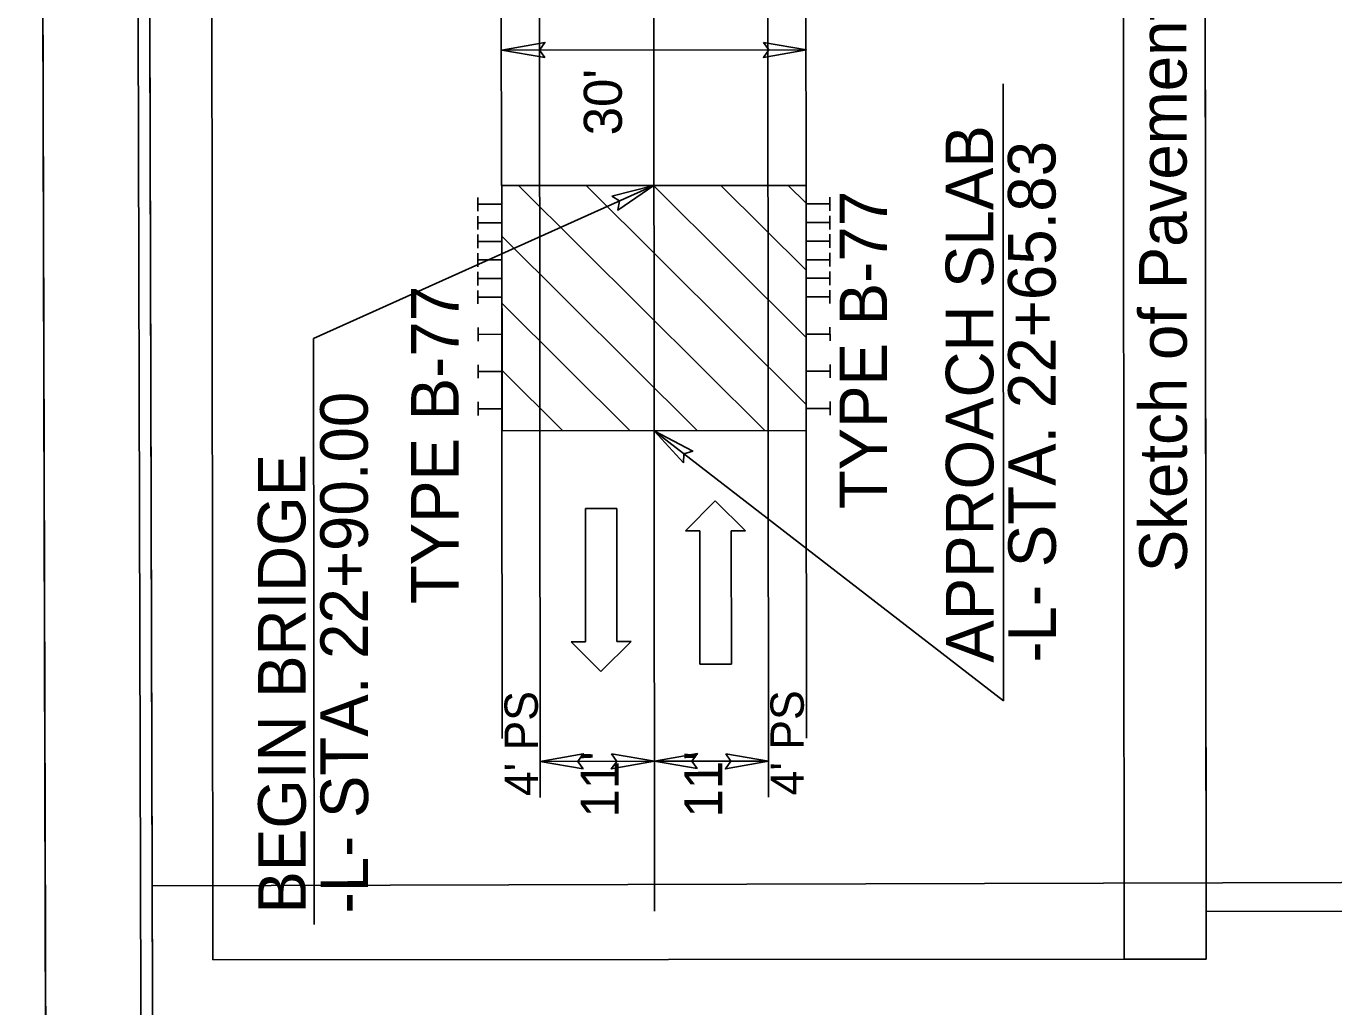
# Model space of a CAD drawing. Extents: x 1373110 to 1374209, y 550682 to 552749.
# Drawn here: x 1373109.6 to 1373384.5, y 551034.3 to 551240.4 of the extents above; entities that cross this region are included whole.
import ezdxf

# ---------------------------------------------------------------- set-up
doc = ezdxf.new("R2010")
doc.units = 0
for name, color, linetype in [('Prop Approach Slab Hatching', 7, 'Continuous'), ('Prop Drainage Structure Drop Inlet Grate 2 Narrow Slots and Flat Grates 840 29 TB Label', 7, 'Continuous'), ('Prop Drainage Structure Gutter Shoulder Berm Label', 7, 'Continuous'), ('Prop Drainage Structure Pipe Alternate 18in', 7, 'Continuous'), ('Prop Drainage Structure Pipe Alternate 18in Label', 7, 'Continuous'), ('Prop Drainage Structure Pipe CSP 15in Label', 7, 'Continuous'), ('Prop Drainage Structure Pipe RCP 15in Class IV Label', 7, 'Continuous'), ('Prop Drainage Structure Pipe Removal Label', 7, 'Continuous'), ('Prop Drainage Structure Tops and Inverts LABEL', 7, 'Continuous'), ('Prop Earthen Structure Base Ditch with Rip Rap Detail CELL', 7, 'Continuous'), ('Prop Earthen Structure Base Ditch with Rip Rap Detail Label', 7, 'Continuous'), ('Prop Earthen Structure V Ditch Special Lateral Detail Label', 7, 'Continuous'), ('Prop Erosion Rip Rap At Embankment Detail Label', 7, 'Continuous'), ('Prop Erosion Rip Rap Class B Label', 7, 'Continuous'), ('Prop Erosion Rip Rap Class I', 7, 'Continuous'), ('Prop Plan Preparation Sketches Hydraulic Ditch', 7, 'Continuous'), ('Prop Roadway Bridge', 7, 'Continuous'), ('Prop SS Fill Line', 7, 'Continuous')]:
    doc.layers.add(name, color=color, linetype=linetype)

msp = doc.modelspace()

# ---------------------------------------------------------------- linework, layer by layer
at = {"layer": 'Prop Approach Slab Hatching'}
for p, q in [((1373209.4, 551306.44), (1373209.49, 551206.85)), ((1373273.53, 551206.9), (1373273.44, 551306.49)), ((1373209.49, 551206.85), (1373273.53, 551206.9))]:
    msp.add_line(p, q, dxfattribs=at)
at = {"layer": 'Prop Drainage Structure Drop Inlet Grate 2 Narrow Slots and Flat Grates 840 29 TB Label'}
for points in [[(1373132.1, 552509.76), (1373136.2, 551009.73), (1374186.2, 551012.6), (1374182.1, 552512.6)], [(1374186.2, 551012.6), (1373136.23, 551009.7), (1373132.64, 552309.68), (1373282.7, 552310.11), (1373282.16, 552510.14), (1374182.1, 552512.6)]]:
    msp.add_lwpolyline(points, close=True, dxfattribs=at)
at = {"layer": 'Prop Drainage Structure Gutter Shoulder Berm Label'}
msp.add_lwpolyline([(1374209.17, 550846.17), (1374204.56, 552529.67), (1373109.57, 552526.67), (1373114.17, 550843.18)], close=True, dxfattribs=at)
at = {"layer": 'Prop Drainage Structure Pipe Alternate 18in'}
for p, q in [((1373209.53, 551206.85), (1373209.57, 551159.97)), ((1373273.53, 551206.9), (1373273.57, 551160.03)), ((1373204.53, 551204.37), (1373204.54, 551201.51)), ((1373209.54, 551202.94), (1373204.54, 551202.94)), ((1373273.53, 551203), (1373278.53, 551203)), ((1373278.53, 551204.43), (1373278.53, 551201.57)), ((1373204.54, 551200.46), (1373204.54, 551197.6)), ((1373278.53, 551200.53), (1373278.53, 551197.66)), ((1373209.54, 551199.04), (1373204.54, 551199.03)), ((1373273.53, 551199.09), (1373278.53, 551199.1)), ((1373204.54, 551196.56), (1373204.54, 551193.69)), ((1373209.54, 551195.13), (1373204.54, 551195.13)), ((1373273.54, 551195.19), (1373278.54, 551195.19)), ((1373278.54, 551196.62), (1373278.54, 551193.76)), ((1373204.54, 551192.65), (1373204.55, 551189.79)), ((1373278.54, 551192.72), (1373278.54, 551189.85)), ((1373209.55, 551191.22), (1373204.55, 551191.22)), ((1373204.55, 551188.74), (1373204.55, 551185.88)), ((1373273.54, 551191.28), (1373278.54, 551191.28)), ((1373278.54, 551188.81), (1373278.54, 551185.95)), ((1373209.55, 551187.32), (1373204.55, 551187.31)), ((1373273.54, 551187.37), (1373278.54, 551187.38)), ((1373204.55, 551184.84), (1373204.55, 551181.97)), ((1373209.55, 551183.41), (1373204.55, 551183.41)), ((1373273.55, 551183.47), (1373278.55, 551183.47)), ((1373278.55, 551184.9), (1373278.55, 551182.04)), ((1373204.56, 551177.03), (1373204.56, 551174.16)), ((1373209.56, 551175.6), (1373204.56, 551175.59)), ((1373273.55, 551175.66), (1373278.55, 551175.66)), ((1373278.55, 551177.09), (1373278.56, 551174.23)), ((1373204.57, 551169.21), (1373204.57, 551166.35)), ((1373209.57, 551167.79), (1373204.57, 551167.78)), ((1373273.56, 551167.84), (1373278.56, 551167.85)), ((1373278.56, 551169.28), (1373278.56, 551166.42)), ((1373204.57, 551161.4), (1373204.57, 551158.54)), ((1373278.57, 551161.47), (1373278.57, 551158.6)), ((1373209.57, 551159.97), (1373204.57, 551159.97)), ((1373273.57, 551160.03), (1373278.57, 551160.03))]:
    msp.add_line(p, q, dxfattribs=at)
at = {"layer": 'Prop Drainage Structure Pipe Alternate 18in Label'}
for points in [[(1373218.59, 551233.8), (1373209.58, 551235.35), (1373218.63, 551236.95), (1373217.48, 551235.35)], [(1373264.58, 551236.94), (1373273.58, 551235.4), (1373264.54, 551233.79), (1373265.68, 551235.4)], [(1373232.68, 551204.6), (1373241.53, 551206.88), (1373233.93, 551201.71), (1373234.32, 551203.64)], [(1373247.75, 551148.59), (1373241.57, 551155.32), (1373249.71, 551151.06), (1373247.82, 551150.49)], [(1373226.63, 551084.3), (1373217.63, 551085.84), (1373226.68, 551087.45), (1373225.53, 551085.84)], [(1373232.63, 551087.4), (1373241.63, 551085.86), (1373232.58, 551084.25), (1373233.73, 551085.85)], [(1373250.63, 551084.32), (1373241.63, 551085.86), (1373250.68, 551087.47), (1373249.53, 551085.87)], [(1373256.63, 551087.42), (1373265.63, 551085.88), (1373256.58, 551084.27), (1373257.73, 551085.87)]]:
    msp.add_lwpolyline(points, close=True, dxfattribs=at)
at = {"layer": 'Prop Drainage Structure Pipe CSP 15in Label'}
msp.add_line((1373109.57, 552526.67), (1373114.17, 550843.18), dxfattribs=at)
at = {"layer": 'Prop Drainage Structure Pipe RCP 15in Class IV Label'}
msp.add_lwpolyline([(1373136.23, 551009.7), (1374186.2, 551012.6), (1374182.1, 552512.59), (1373343.59, 552510.3), (1373344.24, 552271.05), (1373132.76, 552270.47)], close=True, dxfattribs=at)
at = {"layer": 'Prop Drainage Structure Pipe Removal Label'}
for p, q in [((1373209.57, 551159.97), (1373209.64, 551090.66)), ((1373273.63, 551090.72), (1373273.57, 551160.03))]:
    msp.add_line(p, q, dxfattribs=at)
at = {"layer": 'Prop Drainage Structure Tops and Inverts LABEL'}
msp.add_lwpolyline([(1374189.13, 550859.12), (1374184.56, 552525.1), (1373129.58, 552522.23), (1373134.14, 550856.23)], close=True, dxfattribs=at)
at = {"layer": 'Prop Earthen Structure Base Ditch with Rip Rap Detail CELL'}
msp.add_lwpolyline([(1374186.06, 551062.6), (1374182.23, 552462.6), (1373343.73, 552460.31), (1373344.24, 552271.05), (1373132.76, 552270.47), (1373136.07, 551059.72)], close=True, dxfattribs=at)
at = {"layer": 'Prop Earthen Structure V Ditch Special Lateral Detail Label'}
for p, q in [((1373217.64, 551078.27), (1373217.32, 551435.22)), ((1373265.64, 551078.31), (1373265.32, 551435.27))]:
    msp.add_line(p, q, dxfattribs=at)
at = {"layer": 'Prop Erosion Rip Rap At Embankment Detail Label'}
for p, q in [((1373273.53, 551206.9), (1373209.53, 551206.85)), ((1373273.53, 551206.9), (1373209.57, 551206.85)), ((1373209.57, 551206.85), (1373209.61, 551155.29)), ((1373273.57, 551155.35), (1373273.53, 551206.9)), ((1373209.61, 551155.29), (1373273.57, 551155.35))]:
    msp.add_line(p, q, dxfattribs=at)
at = {"layer": 'Prop Erosion Rip Rap Class B Label'}
for points in [[(1374186.06, 551062.6), (1374182.23, 552462.6), (1373343.73, 552460.31), (1373344.24, 552271.05), (1373132.76, 552270.47), (1373136.07, 551059.72)], [(1374186.13, 551055.1), (1374185.31, 551891.66), (1374039.33, 551891.53), (1374038.82, 552461.52), (1373346.29, 552460.9), (1373346.46, 552271.64), (1373134.97, 552271.45), (1373135.76, 551468.67), (1373357.23, 551468.89), (1373357.64, 551054.29)]]:
    msp.add_lwpolyline(points, close=True, dxfattribs=at)
at = {"layer": 'Prop Erosion Rip Rap Class I'}
for p, q in [((1373248.2, 551134.3), (1373254.39, 551140.61)), ((1373254.39, 551140.61), (1373260.8, 551134.31)), ((1373233.72, 551139.01), (1373227.12, 551139)), ((1373227.12, 551139), (1373227.15, 551111)), ((1373233.75, 551111.01), (1373233.72, 551139.01)), ((1373251.2, 551134.3), (1373248.2, 551134.3)), ((1373251.22, 551106.3), (1373251.2, 551134.3)), ((1373260.8, 551134.31), (1373257.8, 551134.31)), ((1373257.8, 551134.31), (1373257.82, 551106.31)), ((1373227.15, 551111), (1373224.15, 551111)), ((1373224.15, 551111), (1373230.35, 551104.71)), ((1373230.35, 551104.71), (1373236.75, 551111.01)), ((1373236.75, 551111.01), (1373233.75, 551111.01)), ((1373257.82, 551106.31), (1373251.22, 551106.3))]:
    msp.add_line(p, q, dxfattribs=at)
at = {"layer": 'Prop Plan Preparation Sketches Hydraulic Ditch'}
for p, q in [((1373209.58, 551235.35), (1373273.58, 551235.4)), ((1373314.92, 551228.23), (1373315.04, 551098.57)), ((1373241.53, 551206.88), (1373169.99, 551174.71)), ((1373169.99, 551174.71), (1373170.09, 551051.6)), ((1373315.04, 551098.57), (1373241.57, 551155.32)), ((1373217.63, 551085.84), (1373241.63, 551085.86)), ((1373241.63, 551085.86), (1373265.63, 551085.88))]:
    msp.add_line(p, q, dxfattribs=at)
for points in [[(1373148.78, 551044.12), (1373148.41, 551468.7), (1373340.01, 551468.88), (1373340.39, 551044.29)], [(1373340.39, 551044.29), (1373340.01, 551468.88), (1373357.23, 551468.89), (1373357.61, 551044.31)]]:
    msp.add_lwpolyline(points, close=True, dxfattribs=at)
at = {"layer": 'Prop Roadway Bridge'}
msp.add_line((1373241.66, 551054.35), (1373241.31, 551451.98), dxfattribs=at)
at = {"layer": 'Prop SS Fill Line'}
for p, q in [((1373264.89, 551155.34), (1373213.1, 551206.85)), ((1373273.57, 551160.82), (1373227.27, 551206.86)), ((1373273.55, 551174.94), (1373241.44, 551206.88)), ((1373273.54, 551189.05), (1373255.61, 551206.89)), ((1373273.53, 551203.17), (1373269.77, 551206.9)), ((1373250.72, 551155.33), (1373209.58, 551196.25)), ((1373236.56, 551155.32), (1373209.59, 551182.14)), ((1373222.39, 551155.31), (1373209.6, 551168.02))]:
    msp.add_line(p, q, dxfattribs=at)

# ---------------------------------------------------------------- texts
at = {"layer": 'Prop Drainage Structure Pipe Alternate 18in'}
for p in [(1373290.55, 551138.84), (1373200.48, 551118.88)]:
    msp.add_text('TYPE B-77', height=10, rotation=90, dxfattribs=at).set_placement(p)
at = {"layer": 'Prop Earthen Structure Base Ditch with Rip Rap Detail Label'}
for s, p in [('Sketch of Pavement in Relation to Bridge', (1373353.59, 551125.6)), ('APPROACH SLAB', (1373312.94, 551106.59)), ('-L- STA. 22+65.83                ', (1373326.05, 551106.6)), ('-L- STA. 22+90.00              ', (1373181.47, 551053.88)), ('BEGIN BRIDGE', (1373168.36, 551053.87))]:
    msp.add_text(s, height=10, rotation=90.0509, dxfattribs=at).set_placement(p)
at = {"layer": 'Prop Plan Preparation Sketches Hydraulic Ditch'}
for s, height, p in [("30'", 8, (1373234.8, 551217.43)), ("4' PS", 7, (1373217.15, 551078.55)), ("4' PS", 7, (1373273.05, 551078.71)), ("11'", 8, (1373234.15, 551074.06)), ("11'", 8, (1373255.91, 551074.07))]:
    msp.add_text(s, height=height, rotation=90.0509, dxfattribs=at).set_placement(p)

doc.saveas('drawing.dxf')
